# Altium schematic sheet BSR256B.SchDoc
size 431 x 279 mm; Date: Not shown in title block; ApprovedBy: Not shown in title block; CheckedBy: Not shown in title block; Author: Not shown in title block; CompanyName: Not shown in title block; Engineer: Not shown in title block; Organization: Not shown in title block; Address1: Not shown in title block; Address2: Not shown in title block; Address3: Not shown in title block; Address4: Not shown in title block; DocumentNumber: 2; Revision: Use project parameter SCH_Rev; SheetNumber: 1; SheetTotal: 2; PageSetup: Record=PageOptions¦CenterHorizontal=True¦CenterVertical=True¦PrintScale=1.00¦XCorrection=1.00¦YCorrection=1.00¦PrintKind=0¦BorderSize=5000000¦LeftOffset=0¦BottomOffset=0¦Orientation=2¦PaperLength=1000¦PaperWidth=1000¦Scale=100¦PaperSource=15¦PrintQuality=600¦MediaType=1¦DitherType=10¦PaperKind=Letter¦PrintScaleMode=1
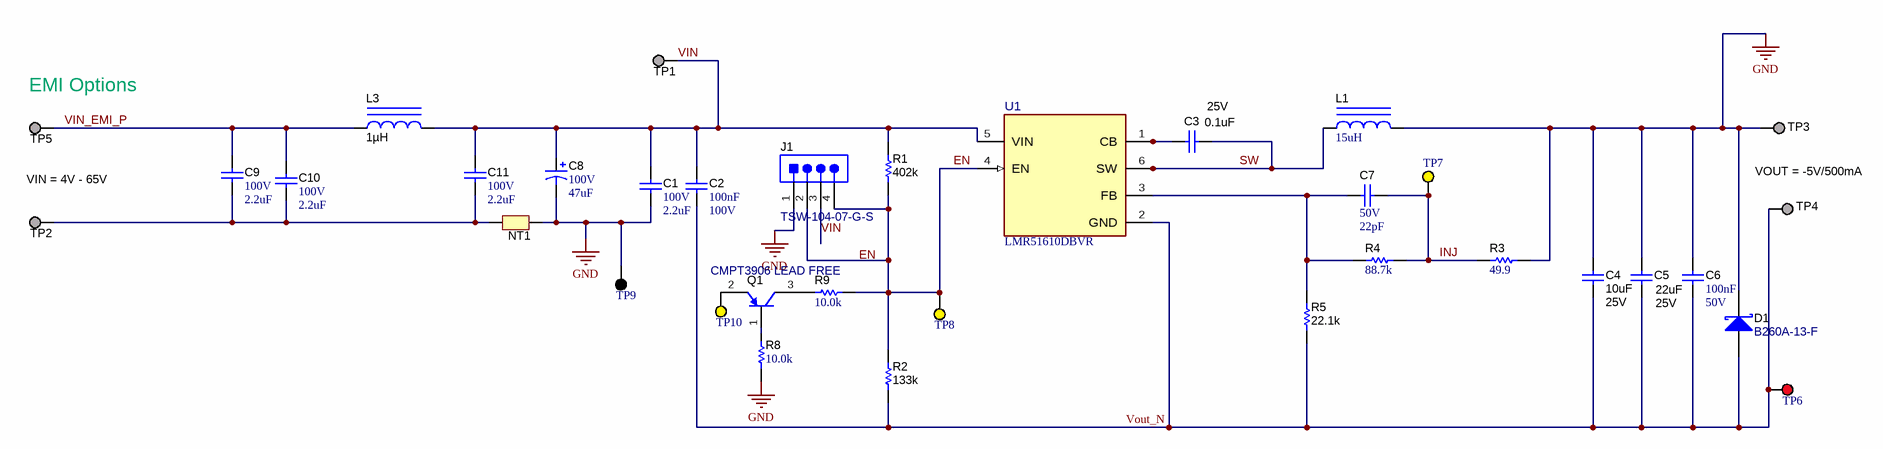
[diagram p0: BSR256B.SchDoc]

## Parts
C1  VDC_V: 100V  ValueDisplayed: 2.2uF  [1206_180]  (hidden comment: C3216X7S2A225K160AB)
C2  Cap_F: 100nF  VDC_V: 100V  [0603]  (hidden comment: GRM188R72A104KA35J)
C3  VDC_V: 25V  ValueDisplayed: 0.1uF  [0402S]  (hidden comment: GRM155R71E104KE14D)
C4  Cap_F: 10uF  VDC_V: 25V  [0805]  (hidden comment: GRM21BZ71E106KE15L)
C5  VDC_V: 25V  ValueDisplayed: 22uF  [1812_280]  (hidden comment: CGA8P1X7R1E226M250KC)
C6  Cap_F: 100nF  VDC_V: 50V  [0603]  (hidden comment: C1608X7R1H104K080AA)
C7  VDC_V: 50V  ValueDisplayed: 22pF  [0603]  (hidden comment: CGA3E2C0G1H220J080AA)
C8  VDC_V: 100V  ValueDisplayed: 47uF  [Panasonic_H13]  (hidden comment: EEV-TG2A470Q)
C9  VDC_V: 100V  ValueDisplayed: 2.2uF  [1206_180]  (hidden comment: C3216X7S2A225K160AB)
C10  VDC_V: 100V  ValueDisplayed: 2.2uF  [1206_180]  (hidden comment: C3216X7S2A225K160AB)
C11  VDC_V: 100V  ValueDisplayed: 2.2uF  [1206_180]  (hidden comment: C3216X7S2A225K160AB)
D1  B260A-13-F  [SMA]
J1  TSW-104-07-G-S  [TSW-104-07-G-S]
L1  ValueDisplayed: 15uH  [WE-LHMI_7050]  (hidden comment: 74437349150)
L3  ValueDisplayed: 1µH  [DFE201612E]  (hidden comment: DFE201612E-1R0M=P2)
NT1  Net-Tie  [Net-Tie_50milWide_30milLong]  (value not drawn)  (net tie, no BOM)
Q1  CMPT3906 LEAD FREE  [SOT-23]
R1  ValueDisplayed: 402k  [0603S]  (hidden comment: CRCW0603402KFKEA)
R2  ValueDisplayed: 133k  [0603S]  (hidden comment: CRCW0603133KFKEA)
R3  ValueDisplayed: 49.9  [0603]  (hidden comment: Resistor)
R4  ValueDisplayed: 88.7k  [0603]  (hidden comment: CRCW060388K7FKEA)
R5  ValueDisplayed: 22.1k  [0603]  (hidden comment: RC0603FR-0722K1L)
R8  ValueDisplayed: 10.0k  [0603]  (hidden comment: ERJ-3EKF1002V)
R9  ValueDisplayed: 10.0k  [0603]  (hidden comment: ERJ-3EKF1002V)
TP1  1502-2  [Keystone1502-2]  (value not drawn)
TP2  1502-2  [Keystone1502-2]  (value not drawn)
TP3  1502-2  [Keystone1502-2]  (value not drawn)
TP4  1502-2  [Keystone1502-2]  (value not drawn)
TP5  1502-2  [Keystone1502-2]  (value not drawn)
TP6  5010  [Keystone5010]  (value not drawn)
TP7  5014  [Keystone5014]  (value not drawn)
TP8  5014  [Keystone5014]  (value not drawn)
TP9  5011  [Keystone5011]  (value not drawn)
TP10  5014  [Keystone5014]  (value not drawn)
U1  LMR51610DBVR  [DBV0006A-MFG]

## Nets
GND: C1.2 C4.1 C5.1 C6.1 C8.2(-) D1.1(K) J1.1 L1.2 NT1.2 R3.1 R8.1 TP3.1 TP9.1
EN: J1.2 J1.4 R1.1 R2.1 R9.1 TP8.1 U1.4(EN)
INJ: C7.1 R3.2 R4.2 TP7.1
SW: C3.1 L1.1 U1.6(SW)
VIN: C1.1 C2.1 C8.1(+) C11.1 J1.3 L3.2 R1.2 TP1.1 U1.5(VIN)
VIN_EMI_P: C9.1 C10.1 L3.1 TP5.1
Vout_N: C2.2 C4.2 C5.2 C6.2 D1.2(A) R2.2 R5.1 TP4.1 TP6.1 U1.2(GND)
NetC3_2: C3.2 U1.1(CB)
NetC7_2: C7.2 R4.1 R5.2 U1.3(FB)
NetC9_2: C9.2 C10.2 C11.2 NT1.1 TP2.1
NetQ1_1: Q1.1(B) R8.2
NetQ1_2: Q1.2(E) TP10.1
NetQ1_3: Q1.3(C) R9.2

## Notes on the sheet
- (near TP5) EMI Options
- VIN = 4V - 65V
- VOUT = -5V/500mA
- Labels drawn without touching a wire or pin: EN

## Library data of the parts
C1 C9-C11 = CMP-0008724-2: CAP, CERM, 2.2 uF, 100 V, +/- 10%, X7S, 1206; Manufacturer: TDK; TaMin_C: -55°C; ESR_ohm: 5.718m; Polarized: N; SizeAreaWB_mm2: 10.92; Value1: 0.005718 ohm; U/M: EA; Value: 2.2uF; TaMax_C: 125°C; SizeZ_mm: 1.8; SizeX_mm: 3.2; SizeY_mm: 1.6; SizeArea_mm2: 5.12; Cap_F: 2.2µF; IRMS_A: 3.03632A; AEC Category: Q200
C2 = CMP-0007470-5: CAP, CERM, 0.1 uF, 100 V, +/- 10%, X7R, 0603; Manufacturer: MuRata; TaMin_C: -55°C; Polarized: N; SizeAreaWB_mm2: 4.68; Value1: Unknown; U/M: EA; Value: 0.1uF; TaMax_C: 125°C; SizeZ_mm: 1; SizeX_mm: 1.6; SizeY_mm: 0.8; SizeArea_mm2: 1.28; AEC Category: Q200
C3 = CMP-0006659-1: CAP, CERM, 0.1 uF, 25 V, +/- 10%, X7R, 0402; Manufacturer: MuRata; TaMin_C: -55°C; Polarized: N; SizeAreaWB_mm2: 3; Value1: Unknown; U/M: EA; Value: 0.1uF; TaMax_C: 125°C; SizeZ_mm: 0.6; SizeX_mm: 1; SizeY_mm: 0.5; Cap_Case: 0402; Cap_F: 100nF; AEC Category: Q200
C4 = CMP-0008378-2: CAP, CERM, 10 uF, 25 V, +/- 10%, X7R, 0805; Manufacturer: MuRata; TaMin_C: -55°C; Polarized: N; SizeAreaWB_mm2: 6.75; Value1: Unknown; U/M: EA; Value: 10uF; TaMax_C: 125°C; SizeZ_mm: 1.45; SizeX_mm: 2; SizeY_mm: 1.25; SizeArea_mm2: 2.5; AEC Category: Q200
C5 = CMP-0009402-2: CAP, CERM, 22 uF, 25 V, +/- 20%, X7R, AEC-Q200 Grade 1,; Manufacturer: TDK; TaMin_C: -55°C; ESR_ohm: 2.434m; Polarized: N; SizeAreaWB_mm2: 23.1; Value1: 0.002434 ohm; U/M: EA; Value: 22uF; TaMax_C: 125°C; SizeZ_mm: 2.8; SizeX_mm: 4.5; SizeY_mm: 3.2; SizeArea_mm2: 14.4; AEC Qualified: Y; Cap_F: 22µF; IRMS_A: 4.91649A; AEC Grade: 1; AEC Category: Q200
C6 = CMP-0007044-3: CAP, CERM, 0.1 uF, 50 V, +/- 10%, X7R, 0603; Manufacturer: TDK; TaMin_C: -55°C; ESR_ohm: 0.0296; Polarized: N; SizeAreaWB_mm2: 4.68; Value1: 0.0296 ohm; U/M: EA; Value: 0.1uF; TaMax_C: 125°C; SizeZ_mm: 1; SizeX_mm: 1.6; SizeY_mm: 0.8; SizeArea_mm2: 1.28; IRMS_A: 971.99mA; AEC Category: Q200
C7 = CMP-0007071-3: CAP, CERM, 22 pF, 50 V, +/- 5%, C0G/NP0, AEC-Q200 Grade 1, 0603; Manufacturer: TDK; TaMin_C: -55°C; Polarized: N; SizeAreaWB_mm2: 4.68; Value1: Unknown; U/M: EA; Value: 22pF; TaMax_C: 125°C; SizeZ_mm: 1; SizeX_mm: 1.6; SizeY_mm: 0.8; SizeArea_mm2: 1.28; AEC Qualified: Y; AEC Category: Q200
C8 = CMP-0011227-2: CAP, AL, 47 uF, 100 V, +/- 20%, 0.42 ohm, AEC-Q200 Grade 1, SMD; Manufacturer: Panasonic; TaMin_C: -40°C; ESR_ohm: 0.42; Polarized: Y; SizeAreaWB_mm2: 240.25; U/M: EA; Value: 47uF; TaMax_C: 125°C; SizeZ_mm: 14; SizeX_mm: 13.5; Cap_Case: 12.5x13.5mm; SizeArea_mm2: 182.25; CompType: Capacitor; Cap_F: 47µF; IRMS_A: 250mA; AEC Grade: 1; AEC Category: Q200
D1 = CMP-0028407-1: Diode, Schottky, 60 V, 2 A, SMA; Manufacturer: Diodes Inc.; Io_A: 2A; Green_Lifecycle: Active; SizeAreaWB_mm2: 37.3428; Vr_V: 60V; Green_REACh: Passed; TJmax_C: 150°C; U/M: EA; Value: 60V; SizeZ_mm: 2.87; SizeX_mm: 5.59; SizeY_mm: 2.92; Vf_V: 700mV; Value2: 0.7V; SizeArea_mm2: 16.3228; AEC Category: Q101; RJC_CperW: 20
J1 = CMP-0075409-2: Header, 100mil, 4x1, Gold, TH; Manufacturer: Samtec; Pitch_mm: 2.54; Cert_VDE: N; Gender: Male; Cert_CSA: Y; Voltage_V: 550V; Green_REACh: Passed; Current_A: 6.3A; Green_Lifecycle: Active; Row_Count: 1
L1 = CMP-0064491-2: Inductor, Shielded Drum Core, Powdered Iron, 15 uH, 2.75 A, 0.092 ohm, SMD; Manufacturer: Wurth Elektronik; Isat: 5.5A @ 20% inductance drop; Irms: 2.75A @ 40C rise; Green_Lifecycle: Active; SizeAreaWB_mm2: 73.96; DCR_ohm: 0.092; Green_REACh: Passed; Value: 15uH; Imax_A: 2.75A; SizeZ_mm: 5; SizeX_mm: 6.6; SizeArea_mm2: 43.56; Ind_H: 15µH; AEC Qualified: N; AEC Category: Q200
L3 = CMP-0080773-1: Inductor, Shielded, Metal Composite, 1 µH, 2.9 A, 0.048 ohm, SMD; Manufacturer: MuRata; Isat: 4A @ 30% inductance drop; Irms: 2.9A @ 40C rise; SizeAreaWB_mm2: 7.8; DCR_ohm: 0.048; Value: 1uH; Imax_A: 2.9A; SizeZ_mm: 1.2; SizeX_mm: 2; SizeY_mm: 1.6; SizeArea_mm2: 3.2; AEC Qualified: N; AEC Category: Q200
NT1 = CMP-0078142-2: Single point connection between nets.
Q1 = CMP-0000320-1: Transistor, PNP, 40 V, 0.2 A, SOT-23; Manufacturer: Central Semiconductor; TaMax_C: 150°C; Value1: 0.2 A; Vcesat1_V: 250mV; SizeX_mm: 2.5; SizeY_mm: 3; TaMin_C: -65°C; IcRated_A: 200mA; CompType: BJT; SizeZ_mm: 1.1; Value: 40 V; SizeArea_mm2: 7.5; NPN: 0; Vceo_V: 40V; PNP: 1; AEC Category: Q101; SizeAreaWB_mm2: 14; U/M: EA
R1 = CMP-0022408-4: RES, 402 k, 1%, 0.1 W, AEC-Q200 Grade 0, 0603; Manufacturer: Vishay-Dale; Value: 402k; Power_W: 100mW; Value2: 0.1W; VDC_V: 75V; TempCo: 100 ppm/C; EIA_Code: E96; SizeX_mm: 1.6; SizeY_mm: 0.8; SizeZ_mm: 1; SizeArea_mm2: 1.28; AEC Qualified: Y; AEC Category: Q200; AEC Grade: 0
R2 = CMP-0022038-4: RES, 133 k, 1%, 0.1 W, AEC-Q200 Grade 0, 0603; Manufacturer: Vishay-Dale; Value: 133k; Power_W: 100mW; Value2: 0.1W; VDC_V: 75V; TempCo: 100 ppm/C; EIA_Code: E96; SizeX_mm: 1.6; SizeY_mm: 0.8; SizeZ_mm: 1; SizeArea_mm2: 1.28; AEC Qualified: Y; AEC Category: Q200; AEC Grade: 0
R3 = CMP-0022448-3: RES, 49.9, 1%, 0.1 W, 0603; PartNumber: CRCW060349R9FKEA; Manufacturer: Vishay-Dale; Value: 49.9; Value_Code: 49R9; Power_W: 100mW; Value2: 0.1W; VDC_V: 75V; TempCo: 100 ppm/C; EIA_Code: E96; U/M: EA; SizeX_mm: 1.6; SizeY_mm: 0.8; SizeZ_mm: 1; SizeArea_mm2: 1.28; AEC Category: Q200
R4 = CMP-0022632-2: RES, 88.7 k, 1%, 0.1 W, 0603; Manufacturer: Vishay-Dale; Power_W: 100mW; TempCo: 100 ppm/C; Value_Code: 88k7; U/M: EA; Value: 88.7k; EIA_Code: E96; SizeX_mm: 1.6; SizeY_mm: 0.8; SizeZ_mm: 1; Value2: 0.1W; SizeArea_mm2: 1.28; VDC_V: 75V; AEC Category: Q200
R5 = CMP-0022923-5: RES, 22.1 k, 1%, 0.1 W, 0603; Manufacturer: Yageo; Power_W: 100mW; TempCo: 100 ppm/C; Value_Code: 22k1; Value: 22.1k; EIA_Code: E96; SizeX_mm: 1.6; SizeY_mm: 0.8; SizeZ_mm: 1; Value2: 0.1W; SizeArea_mm2: 1.28; AEC Qualified: N; VDC_V: 75V; AEC Category: Q200; SizeAreaWB_mm2: 4.68
R8 R9 = CMP-0022684-2: RES, 10.0 k, 1%, 0.1 W, 0603; Manufacturer: Panasonic; Power_W: 100mW; TempCo: 100 ppm/C; Value_Code: 10k0; U/M: EA; Value: 10.0k; EIA_Code: E96; Res_ohm: 10k; SizeX_mm: 1.6; SizeY_mm: 0.8; SizeZ_mm: 1; Value2: 0.1W; SizeArea_mm2: 1.28; VDC_V: 75V; AEC Category: Q200
TP1-TP5 = CMP-0055113-1: Terminal, Turret, TH, Double; Manufacturer: Keystone; CompType: Turret Terminal; CNHeader: FALSE; Green_Lifecycle: Active; Green_REACh: Passed
TP6 = CMP-0055147-1: Test Point, Multipurpose, Red, TH; Manufacturer: Keystone; CNHeader: FALSE; Green_Lifecycle: Active; Green_REACh: Passed; ContactFinish: Silver; CT: TRUE
TP7 TP8 TP10 = CMP-0055151-1: Test Point, Multipurpose, Yellow, TH; Manufacturer: Keystone; CNHeader: FALSE; Green_Lifecycle: Active; Green_REACh: Passed; ContactFinish: Silver; CT: TRUE
TP9 = CMP-0055148-1: Test Point, Multipurpose, Black, TH; Manufacturer: Keystone; CNHeader: FALSE; Green_Lifecycle: Active; Green_REACh: Passed; ContactFinish: Silver; CT: TRUE
U1 = CMP-0096066-1: 65V, 1A Synchronous Step-Down DC-DC Converter; Manufacturer: Texas Instruments; SizeZ_mm: 1.45mm; Max Duty Cycle: 98%; Nominal Supply Current: 25-420uA; Number Of Outputs: 1; Min Supply Voltage: 4V; Switching Frequency: 400/1100kHz; Standoff Height: 0mm; TJmax_C: +150°C; Switching Topology: Buck; Output Voltage: 0.8-28V; Output Type: AdjustableProgrammable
